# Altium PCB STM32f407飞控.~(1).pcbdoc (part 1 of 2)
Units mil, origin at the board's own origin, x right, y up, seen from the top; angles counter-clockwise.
Board outline 2007.87 x 2007.87 mil, 2 copper layers (Top Layer, Bottom Layer); 91 components, 90 nets, 406 pads, 329 vias.
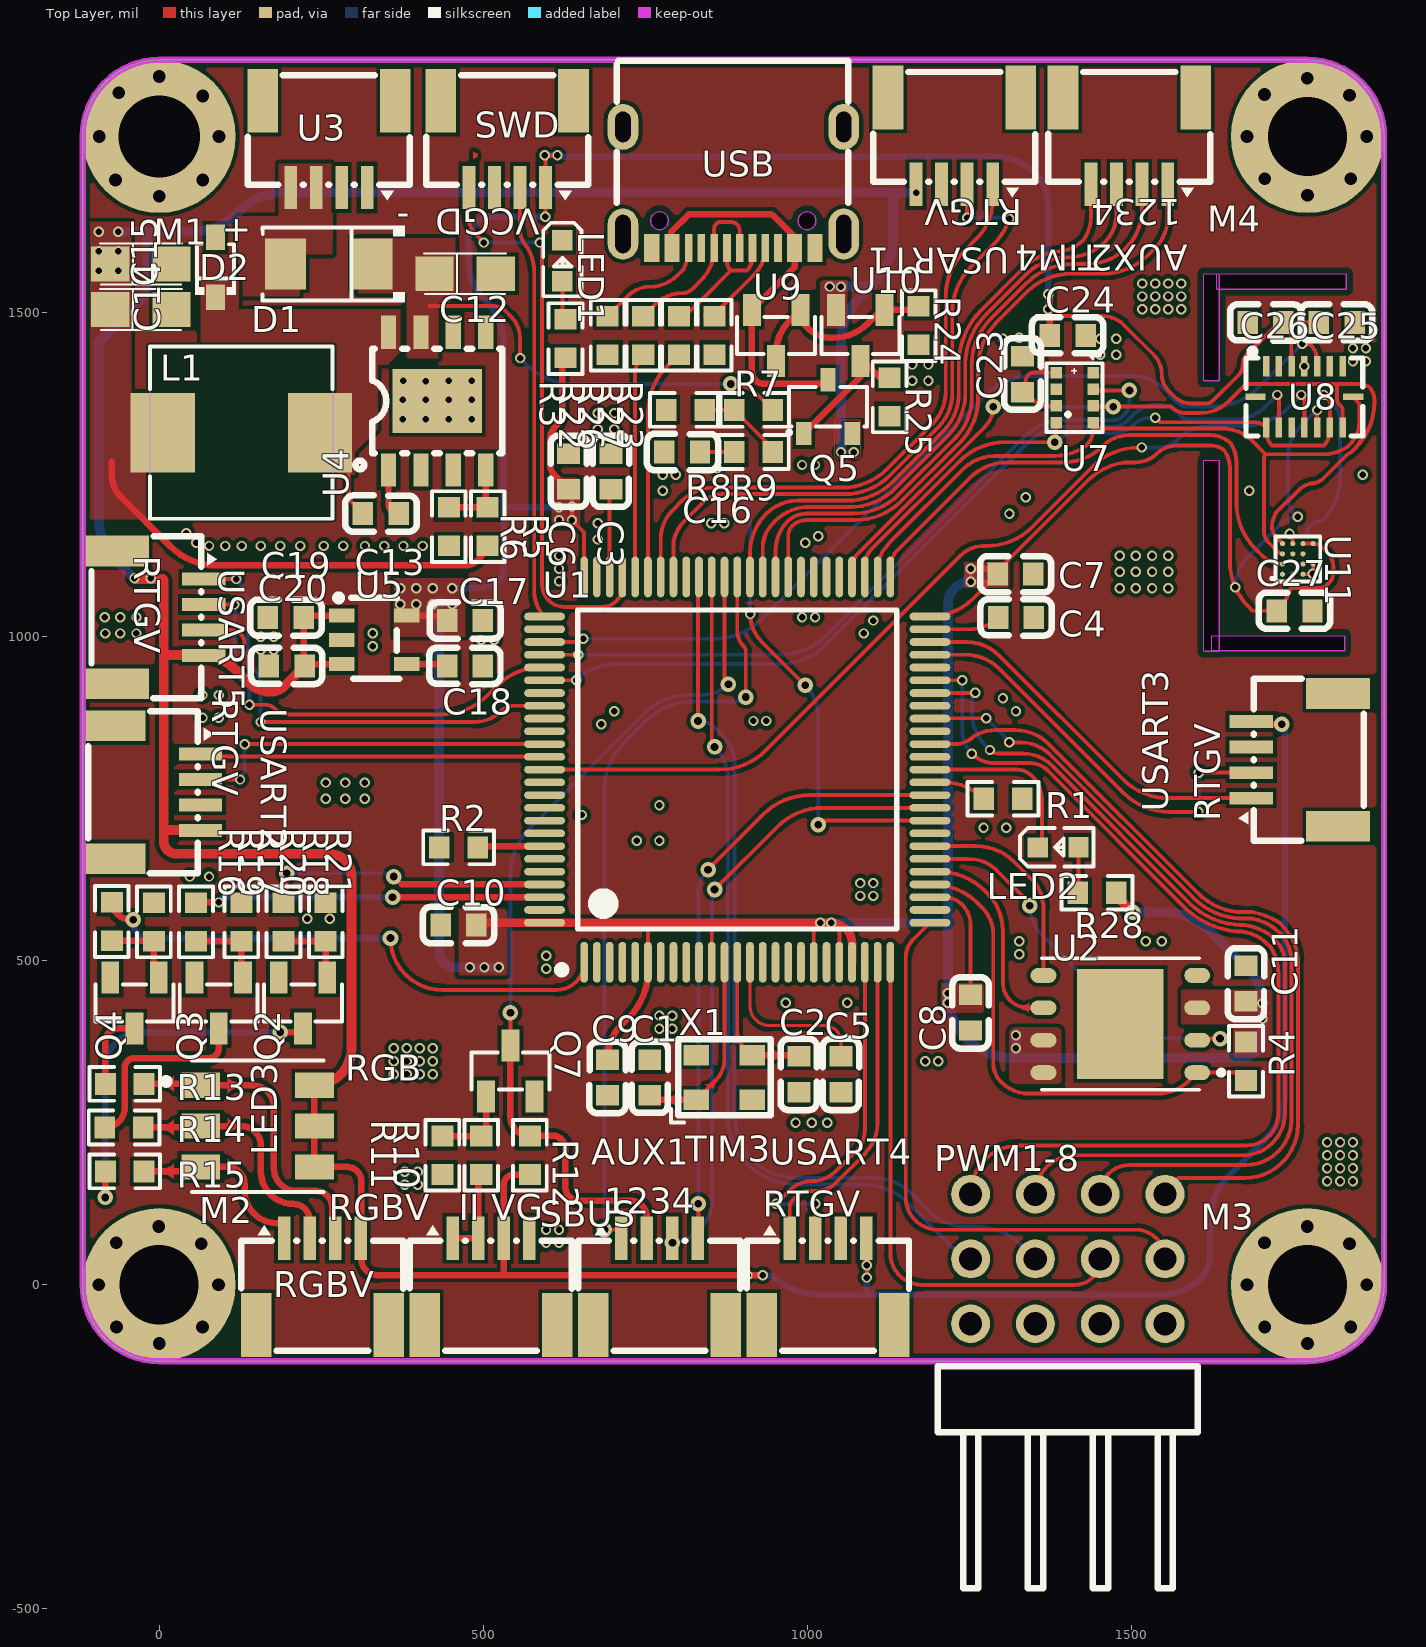
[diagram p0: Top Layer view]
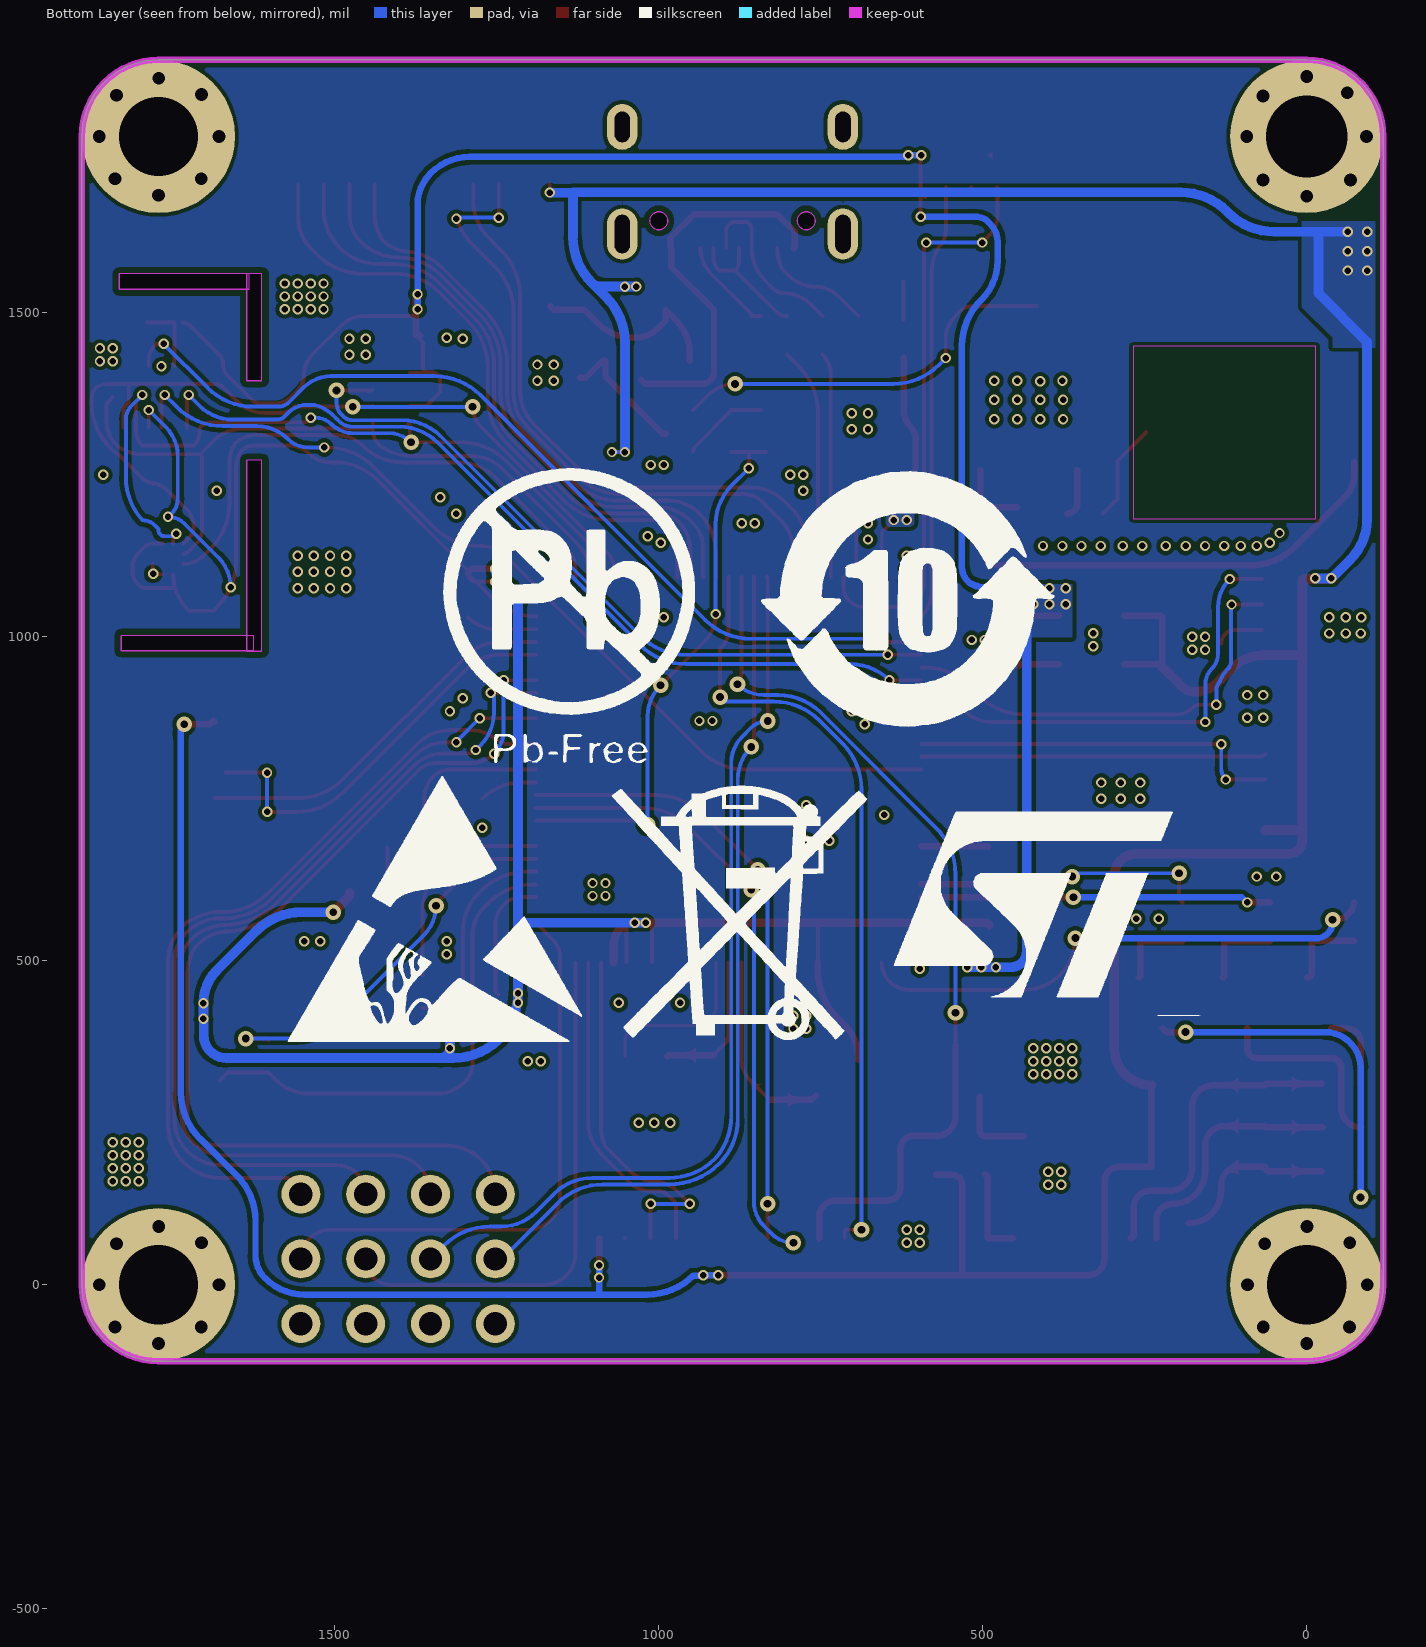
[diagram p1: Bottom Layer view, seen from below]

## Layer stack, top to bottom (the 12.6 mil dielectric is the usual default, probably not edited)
Top Solder Mask Layer: solder mask 0.4, Solder Resist, Dk 3.5
Top Layer: signal copper 1.4
Dielectric1: dielectric 12.6, FR-4, Dk 4.8
Bottom Layer: signal copper 1.4
Bottom Solder Mask Layer: solder mask 0.4, Solder Resist, Dk 3.5

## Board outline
-118.11,0 -118.11,1771.65 cw(c0,1771.65) 0,1889.76 1771.65,1889.76 cw(c1771.65,1771.65) 1889.76,1771.65 1889.76,0 cw(c1771.65,0) 1771.65,-118.11 0,-118.11 cw(c0,0)
cut-out: 1631.89,1559.76 1831.89,1559.76 1831.89,1536.14 1631.89,1536.14
cut-out: 1611.89,1559.76 1635.51,1559.76 1635.51,1394.76 1611.89,1394.76
cut-out: 1611.89,1272.26 1635.51,1272.26 1635.51,977.26 1611.89,977.26
cut-out: 1624.25,977.95 1624.25,1001.57 1829.25,1001.57 1829.25,977.95

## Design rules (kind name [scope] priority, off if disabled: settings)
BoardOutlineClearance copperThickness1oz_1 [All] p1: gap=10 ignorepadtopadclearanceinfootprint=FALSE except(0: Arc-SplitContinuation Track-SplitContinuation SMDPad-OutlineEdge SMDPad-SplitContinuation THPad-OutlineEdge THPad-SplitContinuation Via-SplitContinuation Fill-SplitContinuation Poly-SplitContinuation Region-CutoutEdge Region-SplitContinuation Text-SplitContinuation; 5: Via-OutlineEdge; 6: Track-CutoutEdge SMDPad-CutoutEdge THPad-CutoutEdge Via-CutoutEdge; 11.8: Track-OutlineEdge Fill-OutlineEdge Fill-CutoutEdge Poly-OutlineEdge Region-OutlineEdge Text-OutlineEdge)
BoardOutlineClearance copperThickness2oz_1 [All] p2: gap=10 ignorepadtopadclearanceinfootprint=FALSE except(0: Arc-SplitContinuation Track-SplitContinuation SMDPad-SplitContinuation THPad-SplitContinuation Via-SplitContinuation Fill-SplitContinuation Poly-SplitContinuation Region-SplitContinuation Text-SplitContinuation; 6: Track-CutoutEdge SMDPad-CutoutEdge THPad-CutoutEdge Via-CutoutEdge Region-CutoutEdge; 11.8: Track-OutlineEdge SMDPad-OutlineEdge THPad-OutlineEdge Via-OutlineEdge Fill-OutlineEdge Fill-CutoutEdge Poly-OutlineEdge Region-OutlineEdge Text-OutlineEdge)
Clearance copperThickness1oz [(InNet('$1N2322') OR InNet('GND') OR InNet('$1N2327') OR InNet('$1N2549') OR InNet('$1N2655') OR InNet('NRST') OR InNet('+3V3') OR InNet('VCC_IN') OR InNet('$2N671') OR InNet('$2N634') OR InNet('+5V') OR InNet('POWER_ADC') OR InNet('$2N3106') OR InNet('$2N276') OR InNet('$1N3163') OR InNet('$2N1707') OR InNet('$2N2658') OR InNet('$2N2848') OR InNet('$2N2660') OR InNet('$2N2902') OR InNet('$2N2662') OR InNet('$2N2909') OR InNet('$1N1694') OR InNet('$1N2458') OR InNet('SPI1_NSS') OR InNet('$2N953') OR InNet('$2N1448') OR InNet('SBUS_IN') OR InNet('LED_3') OR InNet('LED_2') OR InNet('LED_1') OR InNet('TIM10_CH1') OR InNet('GYR_INT') OR InNet('USART2_RX') OR InNet('USART2_TX') OR InNet('USART5_RX') OR InNet('SPI2_CS1') OR InNet('USART5_TX') OR InNet('SPI2_CS3') OR InNet('SPI2_CS2') OR InNet('SWCLK') OR InNet('SWDIO') OR InNet('DP') OR InNet('DM') OR InNet('USART1_RX') OR InNet('USART1_TX') OR InNet('TIM8_CH4') OR InNet('TIM8_CH3') OR InNet('TIM3_CH1') OR InNet('TIM4_CH4') OR InNet('TIM4_CH3') OR InNet('TIM4_CH2') OR InNet('TIM4_CH1') OR InNet('SPI2_MISO') OR InNet('SPI2_SCK') OR InNet('SPI2_NSS') OR InNet('TIM1_CH4') OR InNet('TIM1_CH3') OR InNet('TIM1_CH2') OR InNet('TIM1_CH1') OR InNet('TIM3_CH4') OR InNet('TIM3_CH3') OR InNet('SPI1_MOSI') OR InNet('SPI1_MISO') OR InNet('SPI1_SCK') OR InNet('TIM5_CH4') OR InNet('TIM5_CH3') OR InNet('USART4_RX') OR InNet('USART4_TX') OR InNet('X_IO_4') OR InNet('X_IO_1') OR InNet('X_IO_2') OR InNet('X_IO_3') OR InNet('LED_B') OR InNet('LED_G') OR InNet('LED_R') OR InNet('SPI2_MOSI') OR InNet('USART3_RX') OR InNet('USART3_TX') OR InNet('$2N11479') OR InNet('$2N11622') OR InNet('$2N24017') OR InNet('$2N24016') OR InNet('TIM3_CH2') OR InNet('VBUS') OR InNet('$2N11640') OR InNet('$2N11634') OR InNet('LED_4') OR InNet('$1N10901') OR InNet('DRDY'))] p1: gap=6 ignorepadtopadclearanceinfootprint=FALSE except(0: Region-Region; 4: Track-Track; 6.9: Track-Hole SMDPad-Hole THPad-Hole Via-Hole Fill-Hole Poly-Hole Region-Hole Text-Hole; 7: Arc-Arc Arc-Track Arc-SMDPad Arc-THPad Arc-Via Arc-Fill Arc-Poly Arc-Region Arc-Text Arc-Hole; 11.8: Track-Fill Fill-Region)
Clearance copperThickness2oz [All] p2: gap=6 ignorepadtopadclearanceinfootprint=FALSE except(6.9: Track-Hole SMDPad-Hole THPad-Hole Via-Hole Fill-Hole Poly-Hole Region-Hole Text-Hole; 7: Arc-Arc Arc-Track Arc-SMDPad Arc-THPad Arc-Via Arc-Fill Arc-Poly Arc-Region Arc-Text Arc-Hole; 8: Track-Track; 11.8: Track-Fill Fill-Region)
DiffPairsRouting differentialPair [All] p1: maxlimit=6 minlimit=6 mostfreqgap=6 toplayer_minwidth=5 toplayer_maxwidth=100 toplayer_prefwidth=10 bottomlayer_minwidth=5 bottomlayer_maxwidth=100 bottomlayer_prefwidth=10 maxuncoupledlength=10
PasteMaskExpansion pasteMaskExpansion [All] p1: expansion=0
PlaneConnect innerPlane [All] p1: planeconnectstyle=Relief reliefexpansion=20 reliefentries=4 reliefconductorwidth=10 reliefairgap=10
PolygonConnect copperRegion [All] p1: connectstyle=Direct reliefconductorwidth=10 reliefentries=4 polygonreliefangle="90 Angle" airgapwidth=10
RoutingVias viaSize [All] p1: holewidth=12 width=24 viastyle="Through Hole" minholewidth=10 minwidth=16 maxholewidth=248 maxwidth=393.7
SolderMaskExpansion solderMaskExpansion [All] p1: expansion=2 istentingtop=FALSE useseparateexpansions=TRUE expansionbottom=2 istentingbottom=FALSE
Width copperThickness1oz_2 [All] p1: maxlimit=100 minlimit=5 preferedwidth=6
Width copperThickness2oz_2 [All] p2: maxlimit=100 minlimit=8 preferedwidth=10
27 further rules are at their usual default settings.

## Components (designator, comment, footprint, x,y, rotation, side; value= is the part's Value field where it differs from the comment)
C1 "CL10C200JB8NNNC" C0603 756.89,319.76 r270 top
C2 "CL10C200JB8NNNC" C0603 986.89,324.76 r90 top
C3 "CC0603KRX7R9BB104" C0603 696.89,1254.76 r270 top
C4 "CC0603KRX7R9BB104" C0603 1321.89,1029.76 r180 top
C5 "CC0603KRX7R9BB104" C0603 1051.89,324.76 r90 top
C6 "CC0603KRX7R9BB104" C0603 631.89,1254.76 r270 top
C7 "CC0603KRX7R9BB104" C0603 1321.2,1096.34 r180 top
C8 "CC0603KRX7R9BB104" C0603 1251.89,419.76 r90 top
C9 "CC0603KRX7R9BB104" C0603 691.89,319.76 r90 top
C10 "CC0603KRX7R9BB104" C0603 461.89,554.76 r0 top
C11 "CL10A475KO8NNNC" C0603 1676.89,464.76 r90 top
C12 "TAJC107K016RNJ" CAP-SMD_L6.0-W3.2-R-RD 471.89,1559.76 r0 top
C13 "CC0603KRX7R9BB104" C0603 341.89,1189.76 r180 top
C14 "TAJA106K016RNJ" CAP-SMD_L3.2-W1.6-RD-C7171 -28.11,1504.76 r0 top
C15 "TAJA476K006RNJ" CASE-A_3216 -28.11,1574.76 r0 top
C16 "CC0603KRX7R9BB104" C0603 806.89,1284.76 r180 top
C17 "CC0603KRX7R9BB104" C0603 471.89,954.76 r0 top
C18 "CL10A106MA8NRNC" C0603 471.89,1024.76 r180 top
C19 "CC0603KRX7R9BB104" C0603 195.33,1029.23 r180 top
C20 "CL10A475KO8NNNC" C0603 196.89,954.76 r0 top
C23 "CL10A106MA8NRNC" C0603 1331.89,1404.76 r270 top
C24 "CC0603KRX7R9BB104" C0603 1401.89,1464.76 r0 top
C25 "CC0603KRX7R9BB104" C0603 1816.89,1484.76 r0 top
C26 "CC0603KRX7R9BB104" C0603 1706.89,1484.76 r180 top
C27 "CC0603KRX7R9BB104" C0603 1751.89,1039.76 r0 top
D1 "SS34_C8678" SMA_L4.3-W2.6-LS5.2-RD 261.89,1574.76 r180 top
D2 "1N4007WS" SOD-323_L1.8-W1.3-LS2.5-RD 86.89,1569.76 r90 top
L1 "SMMS0630-220M" IND-SMD_L7.3-W6.6_MHCI06030 126.89,1314.76 r0 top
LED1 "19-213/Y2C-CQ2R2L/3T(CY)" LED0603-RD-YELLOW 621.89,1579.76 r270 top
LED2 "19-213/Y2C-CQ2R2L/3T(CY)" LED0603-RD-YELLOW 1386.89,674.76 r0 top
LED3 "XL-5050RGBC-KS" LED-ARRAY-SMD_6P-L5.0-W5.0-TL-RD 151.89,244.76 r0 top
M1 "M3螺丝" m3_bd6.2#1 0,1771.65 r0 top
M2 "M3螺丝" m3_bd6.2#2 0,0 r0 top
M3 "M3螺丝" m3_bd6.2#2 1771.65,0 r0 top
M4 "M3螺丝" m3_bd6.2#2 1771.65,1771.65 r0 top
PWM1-8 "排针 2.54MM 3*4P 弯针" HDR-TH_12P-P2.54-H-M-R3-C4-S2.54-N 1401.89,39.76 r0 top
Q2 "SI2310A" SOT-23-3_L2.9-W1.3-P0.95-LS2.4-BR 221.89,434.76 r90 top
Q3 "SI2310A" SOT-23-3_L2.9-W1.3-P0.95-LS2.4-BR 91.89,434.76 r90 top
Q4 "SI2310A" SOT-23-3_L2.9-W1.3-P0.95-LS2.4-BR -38.11,434.76 r90 top
Q5 "AO3401_C727156" SOT-23-3_L2.9-W1.4-P1.90-LS2.6-BR 1031.89,1354.76 r270 top
Q7 "SS8050_C7420370" SOT-23-3_L2.9-W1.3-P1.90-LS2.4-BR 541.89,329.76 r270 top
R1 "0603WAF1002T5E" R0603 1301.89,749.76 r0 top
R2 "0603WAF1002T5E" R0603 461.89,674.76 r180 top
R3 "0603WAF1002T5E" R0603 626.89,1459.76 r270 top
R4 "0603WAF4701T5E" R0603 1676.89,344.76 r90 top
R5 "0603WAF5102T5E" R0603 506.89,1169.76 r270 top
R6 "0603WAF1502T5E" R0603 446.89,1169.76 r90 top
R7 "0603WAF1002T5E" R0603 916.89,1349.76 r0 top
R8 "0603WAF1001T5E" R0603 811.89,1349.76 r0 top
R9 "0603WAF1001T5E" R0603 916.89,1284.76 r0 top
R10 "0603WAF1001T5E" R0603 496.89,199.76 r270 top
R11 "0603WAF1002T5E" R0603 436.89,199.76 r270 top
R12 "0603WAF1002T5E" R0603 571.89,199.76 r90 top
R13 "0603WAF5100T5E" R0603 -53.11,309.76 r0 top
R14 "0603WAF5100T5E" R0603 -54.18,242.6 r0 top
R15 "0603WAF5100T5E" R0603 -53.11,174.76 r0 top
R16 "0603WAF1001T5E" R0603 -73.11,560.44 r270 top
R17 "0603WAF1001T5E" R0603 56.89,559.76 r270 top
R18 "0603WAF1001T5E" R0603 191.89,559.76 r270 top
R19 "0603WAF1002T5E" R0603 -8.11,559.76 r270 top
R20 "0603WAF1002T5E" R0603 126.89,559.76 r270 top
R21 "0603WAF1002T5E" R0603 256.89,559.76 r270 top
R22 "0603WAF5101T5E" R0603 691.89,1464.76 r270 top
R23 "0603WAF5101T5E" R0603 856.89,1464.76 r270 top
R24 "0603WAF1002T5E" R0603 1171.89,1479.76 r90 top
R25 "0603WAF1002T5E" R0603 1126.89,1369.76 r90 top
R26 "0603WAF1002T5E" R0603 746.89,1464.76 r270 top
R27 "0603WAF1002T5E" R0603 801.89,1464.76 r270 top
R28 "0603WAF1002T5E" R0603 1446.89,604.76 r0 top
RGB "ZX-SH1.0-4PWT" CONN-SMD_4P-P1.00_MEGASTAR_ZX-SH1.0-4PWT 251.89,4.76 r0 top
SBUS "ZX-SH1.0-4PWT" CONN-SMD_4P-P1.00_MEGASTAR_ZX-SH1.0-4PWT 511.89,4.76 r0 top
SWD "ZX-SH1.0-4PWT" CONN-SMD_4P-P1.00_MEGASTAR_ZX-SH1.0-4PWT 536.89,1759.76 r180 top
TIM3 "ZX-SH1.0-4PWT" CONN-SMD_4P-P1.00_MEGASTAR_ZX-SH1.0-4PWT 771.89,4.76 r0 top
TIM4 "ZX-SH1.0-4PWT" CONN-SMD_4P-P1.00_MEGASTAR_ZX-SH1.0-4PWT 1496.89,1764.76 r180 top
U1 "STM32F407VET6" LQFP-100_L14.0-W14.0-P0.50-LS16.0-BL 891.89,794.76 r0 top
U2 "W25Q32JVZPIQ" WSON-8_L6.0-W5.0-P1.27-BL-EP 1482.95,402.22 r90 top
U3 "ZX-SH1.0-4PWT" CONN-SMD_4P-P1.00_MEGASTAR_ZX-SH1.0-4PWT 261.89,1759.76 r180 top
U4 "TPS5430DDAR" ESOP-8_L4.9-W3.9-P1.27-LS6.0-TL-EP 428.82,1363.29 r90 top
U5 "MIC5219-3.3YM5-TR" SOT-23-5_L3.0-W1.7-P0.95-LS2.8-TL 331.89,994.76 r0 top
U7 "SPL06-001_C2684428" SENSOR-SMD_SPL06-001 1412.42,1368.63 r90 top
U8 "BMI088" LGA-16_L4.5-W3.0-P0.50-BL 1766.89,1369.76 r270 top
U9 "SS8550_C7420371" SOT-23-3_L2.9-W1.3-P1.90-LS2.4-BR 951.89,1464.76 r90 top
U10 "SS8550_C7420371" SOT-23-3_L2.9-W1.3-P1.90-LS2.4-BR 1081.89,1464.76 r90 top
U11 "AK09915C" BGA-14_L1.6-W1.6-BR-AK09915C 1756.89,1119.76 r270 top
USART1 "ZX-SH1.0-4PWT" CONN-SMD_4P-P1.00_MEGASTAR_ZX-SH1.0-4PWT 1226.89,1764.76 r180 top
USART2 "ZX-SH1.0-4PWT" CONN-SMD_4P-P1.00_MEGASTAR_ZX-SH1.0-4PWT -3.11,759.76 r270 top
USART3 "ZX-SH1.0-4PWT" CONN-SMD_4P-P1.00_MEGASTAR_ZX-SH1.0-4PWT 1751.89,809.76 r90 top
USART4 "ZX-SH1.0-4PWT" CONN-SMD_4P-P1.00_MEGASTAR_ZX-SH1.0-4PWT 1031.89,4.76 r0 top
USART5 "ZX-SH1.0-4PWT" CONN-SMD_4P-P1.00_MEGASTAR_ZX-SH1.0-4PWT 1.89,1029.76 r270 top
USB "TYPE-C 16PIN 2MD(073)" USB-C-SMD_TYPE-C-6PIN-2MD-073 885.83,1692.91 r180 top
X1 "X32258MOB4SI" OSC-SMD_4P-L3.2-W2.5-BL 871.89,319.76 r0 top

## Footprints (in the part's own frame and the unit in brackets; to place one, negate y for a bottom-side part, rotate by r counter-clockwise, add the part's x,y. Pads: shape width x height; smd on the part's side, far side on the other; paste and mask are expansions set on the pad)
BGA-14_L1.6-W1.6-BR-AK09915C [mm]
  round 0.2 smd: A1(0.6,-0.6) A2(0.2,-0.6) A3(-0.2,-0.6) A4(-0.6,-0.6) B1(0.6,-0.2) B3(-0.2,-0.2) B4(-0.6,-0.2) C1(0.6,0.2) C2(0.2,0.2) C3(-0.2,0.2) C4(-0.6,0.2) D1(0.6,0.6) D2(0.2,0.6) D4(-0.6,0.6)
  silkscreen extent -0.88,-1.07 0.88,0.88
C0603 [mm]
  rect 0.8x0.9 smd: 1(-0.7,0) 2(0.7,0)
  silkscreen extent -1.41,-0.71 1.39,0.72
CAP-SMD_L3.2-W1.6-RD-C7171 [mm]
  rect 1.5x1.359 smd: 1(-1.2,0) 2(1.2,0)
  silkscreen extent -1.6,-0.8 1.6,0.8
CAP-SMD_L6.0-W3.2-R-RD [mil]
  rect 59.05x53.5 smd: 1(-47.24,0) 2(47.24,0)
  silkscreen extent -63,-32 63,32
CASE-A_3216 [mil]
  rect 59.05x53.5 smd: 1(-47.24,0) 2(47.24,0)
  silkscreen extent -63,-32 63,32
CONN-SMD_4P-P1.00_MEGASTAR_ZX-SH1.0-4PWT [mm]
  rect 0.5x1.7 smd paste+0 mask+0.05: 1(-1.5,1.7) 2(-0.5,1.7) 3(0.5,1.7) 4(1.5,1.7)
  rect 1.2x2.5 smd paste+0 mask+0.05: 5(2.6,-1.7) 6(-2.6,-1.7)
  silkscreen extent -3.17,-2.7 3.18,2.21
ESOP-8_L4.9-W3.9-P1.27-LS6.0-TL-EP [mm]
  rect 1.3x0.6 smd: 1(-2.7,1.905) 2(-2.7,0.635) 3(-2.7,-0.635) 4(-2.7,-1.905) 5(2.7,-1.905) 6(2.7,-0.635) 7(2.7,0.635) 8(2.7,1.905)
  rect 2.5x3.5 smd: 9(0,0)
  silkscreen extent -2.67,-2.55 2.05,3.2
HDR-TH_12P-P2.54-H-M-R3-C4-S2.54-N [mil]
  round 60 hole 36 paste+0 mask+1.97: 1(-150,100) 2(-50,100) 3(50,100) 4(150,100) 5(150,0) 6(50,0) 7(-50,0) 8(-150,0) 9(-150,-100) 10(-50,-100) 11(50,-100) 12(150,-100)
  silkscreen extent -201,-508 201,-165
IND-SMD_L7.3-W6.6_MHCI06030 [mm]
  rect 2.524x3.12 smd: 1(-3.078,0) 2(3.078,0)
  silkscreen extent -3.58,-3.38 3.58,3.38
LED0603-RD-YELLOW [mm]
  rect 0.8x0.8 smd: 1(-0.799,-0.003) 2(0.799,0.003)
  silkscreen extent -1.49,-0.75 1.39,0.76
LED-ARRAY-SMD_6P-L5.0-W5.0-TL-RD [mil]
  rect 60x38.58 smd: 1(-87.7,62.99) 2(-87.7,0) 3(-87.7,-62.99) 4(87.7,-62.99) 5(87.7,0) 6(87.7,62.99)
  silkscreen extent -146,-101 101,101
LGA-16_L4.5-W3.0-P0.50-BL [mm]
  rect 0.8x0.25 smd: 1(-1.2,-1.498) 2(-1.2,-0.998) 3(-1.2,-0.498) 4(-1.2,0.002) 5(-1.2,0.502) 6(-1.2,1.002) 7(-1.2,1.502) 9(1.2,1.502) 10(1.2,1.002) 11(1.2,0.502) 12(1.2,0.002) 13(1.2,-0.498) 14(1.2,-0.998) 15(1.2,-1.498)
  rect 0.25x0.8 smd: 8(0,1.915) 16(0,-1.915)
  silkscreen extent -1.89,-2.29 1.52,2.29
LQFP-100_L14.0-W14.0-P0.50-LS16.0-BL [mm]
  oval 0.3x1.6 smd paste-100 mask+0.051: 1(-6,-7.55) 2(-5.5,-7.55) 3(-5,-7.55) 4(-4.5,-7.55) 5(-4,-7.55) 6(-3.5,-7.55) 7(-3,-7.55) 8(-2.5,-7.55) 9(-2,-7.55) 10(-1.5,-7.55) 11(-1,-7.55) 12(-0.5,-7.55) 13(0,-7.55) 14(0.5,-7.55) 15(1,-7.55) 16(1.5,-7.55) 17(2,-7.55) 18(2.5,-7.55) 19(3,-7.55) 20(3.5,-7.55) 21(4,-7.55) 22(4.5,-7.55) 23(5,-7.55) 24(5.5,-7.55) 25(6,-7.55) 51(6,7.55) 52(5.5,7.55) 53(5,7.55) 54(4.5,7.55) 55(4,7.55) 56(3.5,7.55) 57(3,7.55) 58(2.5,7.55) 59(2,7.55) 60(1.5,7.55) 61(1,7.55) 62(0.5,7.55) 63(0,7.55) 64(-0.5,7.55) 65(-1,7.55) 66(-1.5,7.55) 67(-2,7.55) 68(-2.5,7.55) 69(-3,7.55) 70(-3.5,7.55) 71(-4,7.55) 72(-4.5,7.55) 73(-5,7.55) 74(-5.5,7.55) 75(-6,7.55)
  oval 1.6x0.3 smd paste-100 mask+0.051: 26(7.55,-6) 27(7.55,-5.5) 28(7.55,-5) 29(7.55,-4.5) 30(7.55,-4) 31(7.55,-3.5) 32(7.55,-3) 33(7.55,-2.5) 34(7.55,-2) 35(7.55,-1.5) 36(7.55,-1) 37(7.55,-0.5) 38(7.55,0) 39(7.55,0.5) 40(7.55,1) 41(7.55,1.5) 42(7.55,2) 43(7.55,2.5) 44(7.55,3) 45(7.55,3.5) 46(7.55,4) 47(7.55,4.5) 48(7.55,5) 49(7.55,5.5) 50(7.55,6) 76(-7.55,6) 77(-7.55,5.5) 78(-7.55,5) 79(-7.55,4.5) 80(-7.55,4) 81(-7.55,3.5) 82(-7.55,3) 83(-7.55,2.5) 84(-7.55,2) 85(-7.55,1.5) 86(-7.55,1) 87(-7.55,0.5) 88(-7.55,0) 89(-7.55,-0.5) 90(-7.55,-1) 91(-7.55,-1.5) 92(-7.55,-2) 93(-7.55,-2.5) 94(-7.55,-3) 95(-7.55,-3.5) 96(-7.55,-4) 97(-7.55,-4.5) 98(-7.55,-5) 99(-7.55,-5.5) 100(-7.55,-6)
  silkscreen extent -7.03,-8 6.25,6.25
m3_bd6.2#1 [mm]
  round 6 hole 3.2: 1(0,0)
m3_bd6.2#2 [mm]
  round 6 hole 3.1: 1(0,0)
OSC-SMD_4P-L3.2-W2.5-BL [mm]
  rect 1x0.8 smd: 1(-1.1,-0.875) 2(1.1,-0.875) 3(1.1,0.875) 4(-1.1,0.875)
  silkscreen extent -2.08,-1.77 1.83,1.5
R0603 [mil]
  rect 31.75x34.02 smd paste-3937.01 mask+2: 1(-29.66,0) 2(29.66,0)
  silkscreen extent -55,-26 55,26
SENSOR-SMD_SPL06-001 [mm]
  rect 0.45x0.45 smd: 1(0.975,-0.725) 2(0.325,-0.725) 3(-0.325,-0.725) 4(-0.975,-0.725) 5(-0.975,0.725) 6(-0.325,0.725) 7(0.325,0.725) 8(0.975,0.725)
  silkscreen extent -1.35,-1.1 1.64,1.1
SMA_L4.3-W2.6-LS5.2-RD [mm]
  rect 1.6x2 smd: 1(-1.7,-0.008) 2(1.7,-0.009)
  silkscreen extent -2.98,-1.5 2.6,1.5
SOD-323_L1.8-W1.3-LS2.5-RD [mm]
  rect 1x0.75 smd: 1(-1.173,0) 2(1.173,0)
  silkscreen extent -1.08,-0.8 0.9,0.8
SOT-23-3_L2.9-W1.3-P0.95-LS2.4-BR [mm]
  rect 1.25x0.7 smd: 1(1,-0.95) 2(1,0.95) 3(-1,0)
  silkscreen extent -0.73,-1.53 0.73,1.53
SOT-23-3_L2.9-W1.3-P1.90-LS2.4-BR [mm]
  rect 1.25x0.7 smd: 1(1,-0.95) 2(1,0.95) 3(-1,0)
  silkscreen extent -0.73,-1.53 0.73,1.53
SOT-23-3_L2.9-W1.4-P1.90-LS2.6-BR [mm]
  rect 0.91x0.6 smd: 1(1.055,-0.955) 2(1.055,0.955) 3(-1.055,0)
  silkscreen extent -0.78,-1.6 1.09,1.53
SOT-23-5_L3.0-W1.7-P0.95-LS2.8-TL [mm]
  rect 1x0.55 smd: 1(-1.271,0.95) 2(-1.271,0) 3(-1.271,-0.95) 4(1.271,-0.95) 5(1.271,0.95)
  silkscreen extent -1.52,-1.52 0.97,1.78
USB-C-SMD_TYPE-C-6PIN-2MD-073 [mm]
  rect 0.6x1.1 smd paste-100 mask+0.05: 1(-3.2,2.375) 2(-2.4,2.375) 11(2.4,2.375) 12(3.2,2.375)
  rect 0.3x1.1 smd paste-100 mask+0.05: 3(-1.75,2.375) 4(-1.25,2.375) 5(-0.75,2.375) 6(-0.25,2.375) 7(0.25,2.375) 8(0.75,2.375) 9(1.25,2.375) 10(1.75,2.375)
  oval 1.2x1.8 hole 0.6 slot 1.2 at 90 deg paste+0 mask+0.05: 13(-4.325,-2.375) 14(4.325,-2.375)
  oval 1.2x2 hole 0.6 slot 1.5 at 90 deg paste+0 mask+0.05: 13(-4.325,1.825) 13(4.325,1.825)
  Board Outline Layer board cut-out: -3.24,1.305 -3.24,1.375 -3.187,1.503 -3.088,1.602 -2.96,1.655 -2.82,1.655 -2.692,1.602 -2.593,1.503 -2.54,1.375 -2.54,1.305 -2.54,1.235 -2.593,1.107 -2.692,1.008 -2.82,0.955 -2.96,0.955 -3.088,1.008 -3.187,1.107 -3.24,1.235 -3.24,1.305
  Board Outline Layer board cut-out: 2.54,1.305 2.54,1.375 2.593,1.503 2.692,1.602 2.821,1.655 2.96,1.655 3.088,1.602 3.187,1.503 3.24,1.375 3.24,1.305 3.24,1.235 3.187,1.107 3.088,1.008 2.96,0.955 2.821,0.955 2.692,1.008 2.593,1.107 2.54,1.235 2.54,1.305
  Board Outline Layer circle w0.025: c-2.89,1.305 r0.35
  Board Outline Layer circle w0.025: c2.89,1.305 r0.35
  Board Outline Layer region: -3.24,1.305 -3.24,1.375 -3.187,1.503 -3.088,1.602 -2.96,1.655 -2.82,1.655 -2.692,1.602 -2.593,1.503 -2.54,1.375 -2.54,1.305 -2.54,1.235 -2.593,1.107 -2.692,1.008 -2.82,0.955 -2.96,0.955 -3.088,1.008 -3.187,1.107 -3.24,1.235 -3.24,1.305
  Board Outline Layer region: 2.54,1.305 2.54,1.375 2.593,1.503 2.692,1.602 2.821,1.655 2.96,1.655 3.088,1.602 3.187,1.503 3.24,1.375 3.24,1.305 3.24,1.235 3.187,1.107 3.088,1.008 2.96,0.955 2.821,0.955 2.692,1.008 2.593,1.107 2.54,1.235 2.54,1.305
  silkscreen extent -4.5,-4.97 4.57,0.6
WSON-8_L6.0-W5.0-P1.27-BL-EP [mil]
  oval 22.87x40 smd: 1(-75,-118.61) 2(-25,-118.61) 3(25,-118.61) 4(75,-118.61) 5(75,118.61) 6(25,118.61) 7(-25,118.61) 8(-75,118.61)
  rect 169.29x133.86 smd: 9(0,0)
  silkscreen extent -101,-159 101,121

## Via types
v1: diameter 16, hole 10, Top Layer to Bottom Layer, 269 vias
v2: diameter 31.5, hole 19.69, Top Layer to Bottom Layer, 32 vias
v3: diameter 24, hole 12, Top Layer to Bottom Layer, 23 vias
v4: diameter 24.02, hole 12.01, Top Layer to Bottom Layer, 5 vias

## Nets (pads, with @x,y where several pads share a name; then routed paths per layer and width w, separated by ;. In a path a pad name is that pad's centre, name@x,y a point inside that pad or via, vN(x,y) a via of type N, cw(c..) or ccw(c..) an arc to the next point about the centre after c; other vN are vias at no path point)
$1N1694: R1.1 U1.37 | length 89.9
  Top Layer w6: U1.37@1189.13,775.08 1211.1,775.08 cw(c1211.1,688.64) 1218.53,774.76 cw(c1211.1,688.64) R1.1@1272.23,749.76
$1N2322: C1.2 U1.12 X1.1 | length 302.9
  Top Layer w6: X1.1@828.58,285.31 859.09,315.83 ccw(c828.19,346.72) 871.89,346.72 871.89,382.87 cw(c872.98,382.87) 872.21,383.64 U1.12@872.21,497.52
  Top Layer w10: C1.2@756.89,292.2 763.78,285.31 X1.1@828.58,285.31
$1N2327: C2.2 U1.13 X1.3 | length 225.4
  Top Layer w6: U1.13@891.89,497.52 891.89,377.52 X1.3@915.2,354.21
  Top Layer w10: X1.3@915.2,354.21 985,354.21 C2.2@986.89,352.32
$1N2458: R2.1 U1.94 | length 104.2
  Top Layer w10: R2.1@491.55,674.76 cw(c493.44,674.76) 493.44,676.65 U1.94@594.65,676.65
$1N2549: C3.2 U1.73 | length 136
  Top Layer w6: U1.73@695.04,1092 695.04,1225.35 C3.2@696.89,1227.2
$1N2655: C4.2 U1.49 | length 110.1
  Top Layer w6: U1.49@1189.13,1011.3 1249.76,1011.3 ccw(c1249.76,1074.33) 1277.11,1017.55 ccw(c1249.76,1074.33) C4.2@1294.33,1029.76
$1N3163: LED1.2 R3.1 | length 58.9
  Top Layer w6: R3.1@621.89,1489.42 622.02,1489.56 LED1.2@622.02,1548.29
$1N10901: LED2.2 R28.1 | length 70.4
  Top Layer w6: R28.1@1417.23,604.76 ccw(c1414.49,607.5) R28.1@1418.36,607.5 ; R28.1@1418.36,607.5 LED2.2@1418.36,674.9
$2N276: D1.2 U3.3 U3.4
$2N634: C13.1 U4.1 | length 76.2
  Top Layer w10: U4.1@353.82,1257 353.82,1205.39 ccw(c369.45,1205.39) C13.1@369.45,1189.76
$2N671: C13.2 D2.1 L1.2 U4.8 | length 152.4
  Top Layer w6: L1.2@248.07,1314.76 291.89,1270.94 291.89,1212.2 C13.2@314.33,1189.76
$2N953: R5.1 R6.2 U4.4 | length 113.7
  Top Layer w10: R6.2@446.89,1199.42 501.89,1199.42 ccw(c501.89,1201.35) 503.82,1201.35 U4.4@503.82,1257
$2N1448: R7.1 R8.2 R9.2 | length 134.7
  Top Layer w6: R8.2@841.55,1349.76 R7.1@887.23,1349.76 942.53,1294.46 cw(c932.84,1284.76) R9.2@946.55,1284.76
$2N1707: Q7.1 R10.1 R11.1 | length 125.3
  Top Layer w10: R11.1@436.89,229.42 R10.1@496.89,229.42 ccw(c496.89,237.02) 504.49,237.02 Q7.1@504.49,290.39
$2N2658: Q2.1 R18.2 R21.2 | length 122.3
  Top Layer w10: R18.2@191.89,530.1 R21.2@256.89,530.1 256.89,476.53 ccw(c259.29,476.53) Q2.1@259.29,474.13
$2N2660: Q3.1 R17.2 R20.2 | length 127.3
  Top Layer w10: R17.2@56.89,530.1 R20.2@126.89,530.1 126.89,476.53 ccw(c129.29,476.53) Q3.1@129.29,474.13
$2N2662: Q4.1 R16.2 R19.2 | length 125.6
  Top Layer w10: R16.2@-73.11,530.78 -8.79,530.78 cw(c-8.79,530.1) R19.2@-8.11,530.1 -8.11,481.53 ccw(c-0.71,481.53) Q4.1@-0.71,474.13
$2N2848: Q2.3 R15.1 | length 579
  Top Layer w10: v4(-83.11,134.76) -83.11,174.42 R15.1@-82.77,174.76 ; v4(186.89,389.76) 216.26,389.76 221.26,394.76 ccw(c221.26,395.39) Q2.3@221.89,395.39
  Bottom Layer w10: v4(-83.11,134.76) -83.11,334.76 cw(c-28.11,334.76) -28.11,389.76 v4(186.89,389.76)
$2N2902: Q3.3 R14.1 | length 302.5
  Top Layer w10: R14.1@-83.84,242.6 ccw(c-83.84,273.33) -53.11,273.33 -53.11,334.76 cw(c-38.11,334.76) -38.11,349.76 76.89,349.76 ccw(c76.89,364.76) 91.89,364.76 Q3.3@91.89,395.39
$2N2909: Q4.3 R13.1 | length 122
  Top Layer w10: R13.1@-82.77,309.76 cw(c-82.77,310.1) -83.11,310.1 -83.11,374.76 cw(c-62.48,374.76) -62.48,395.39 Q4.3@-38.11,395.39
$2N3106: C17.1 U5.4 | length 63.9
  Top Layer w10: U5.4@381.94,957.36 441.73,957.36 cw(c441.73,954.76) C17.1@444.33,954.76
$2N11479: R22.1 USB.10 | length 176.4
  Top Layer w6: R22.1@691.89,1494.42 723.33,1525.86 cw(c756.89,1492.3) 756.89,1539.76 ccw(c756.89,1600.89) 800.11,1557.67 808.84,1566.4 ccw(c745.43,1599.41) USB.10@816.92,1599.41
$2N11622: R23.1 USB.4 | length 146.4
  Top Layer w6: R23.1@841.89,1494.42 R23.1@853.67,1494.42 ; R23.1@856.89,1494.42 cw(c864.67,1494.42) 859.17,1499.93 918.33,1559.09 ccw(c878.01,1599.41) 919.83,1560.64 ccw(c878.01,1599.41) 927.74,1571.52 ccw(c921.26,1577.75) 930.14,1576.3 ccw(c878.01,1599.41) USB.4@935.03,1599.41
$2N11634: R26.1 USB.6 USB.8 | length 273.2
  Top Layer w6: R26.1@746.89,1494.42 764.79,1512.33 cw(c806.89,1470.23) 806.89,1529.76 ccw(c806.89,1552.32) 822.84,1536.37 835.39,1548.92 ccw(c784.9,1599.41) USB.8@856.3,1599.41 856.3,1629.18 cw(c866.89,1629.18) 866.89,1639.76 881.89,1639.76 cw(c881.89,1625.98) 895.67,1625.98 USB.6@895.67,1599.41
$2N11640: R27.1 USB.5 USB.7 | length 206.3
  Top Layer w6: R27.1@801.89,1494.42 ccw(c801.89,1517.75) 818.38,1501.25 832.35,1515.22 cw(c839.88,1510.3) 834.96,1517.83 881.89,1564.76 ; USB.7@875.98,1599.41 875.98,1579.03 ccw(c896.15,1579.03) 881.89,1564.76 ; USB.5@915.35,1599.41 915.35,1585.19 cw(c886.46,1585.19) 906.89,1564.76 881.89,1564.76
$2N24016: R24.2 U9.1 U9.3 U10.1 | length 311.2
  Top Layer w10: U9.3@951.89,1425.39 951.89,1437.06 cw(c1023.52,1437.06) 972.87,1487.72 U9.1@989.29,1504.13 989.29,1487.36 1001.62,1475.03 ccw(c1035.5,1508.91) 1035.5,1461 1039.62,1461 ccw(c1039.62,1537.13) 1093.45,1483.3 1114.29,1504.13 1161.6,1504.13 R24.2@1166.89,1509.42
$2N24017: Q5.1 R25.2 U10.3 | length 204.2
  Top Layer w10: Q5.1@989.29,1313.22 Q5.1@994.29,1313.22 1081.89,1400.82 U10.3@1081.89,1425.39 1086.26,1425.39 1112.23,1399.42 R25.2@1121.89,1399.42
+3V3: C6.2 C7.2 C8.2 C9.2 C10.2 C11.1 C18.2 C23.2 C24.1 C25.1 C26.1 C27.1 R3.2 R4.2 R28.2 SWD.1 U1.6 U1.11 U1.19 U1.21 U1.22 U1.28 U1.50 U1.75 U1.100 U2.3 U2.7 U2.8 U5.5 U7.6 U7.8 U8.3 U8.11 U11.B1 U11.C4 U11.D4 | length 8543.3
  Top Layer w6: SWD.1@588.65,1678.22 SWD.1@590.76,1680.32 ; v1(595.56,1647.98) ccw(c594.64,1648.9) 595.94,1648.9 SWD.1@595.94,1692.83 595.94,1739.2 ccw(c591.39,1739.2) v1(594.61,1742.42) v1(614.54,1742.42) ; C6.2@636.89,1222.2 v1(636.89,1179.76) 655.67,1160.98 U1.75@655.67,1092 ; 753.33,558.54 cw(c753.33,557.79) 754.09,557.79 U1.6@754.09,497.52 ; 851.28,558.54 cw(c851.28,557.3) 852.52,557.3 U1.11@852.52,497.52 ; 1008.69,558.54 cw(c1008.69,557.23) 1010,557.23 U1.19@1010,497.52 ; 1048.46,556.33 cw(c1048.46,555.43) 1049.09,556.08 cw(c1048.46,555.43) 1049.37,555.43 U1.21@1049.37,497.52 ; U1.28@1189.13,597.91 1211.45,597.91 cw(c1211.45,559.27) 1238.78,586.59 cw(c1207.11,554.93) 1251.89,554.93 1251.89,452.32 C8.2@1246.89,447.32 ; U1.50@1189.13,1030.98 ccw(c1189.13,1125.5) 1255.96,1058.67 C7.2@1282.06,1084.76 ; v1(1251.89,1104.76) v1(1251.89,1084.76) C7.2@1282.06,1084.76 ; v1(1371.89,1504.76) v1@1374.33,1502.32 ; C24.1@1374.33,1473.25 1365.84,1464.76 C24.1@1374.33,1464.76 1362.3,1452.74 cw(c1354.61,1448.07) 1363.61,1448.07 1363.61,1416.58 cw(c1354.61,1416.58) 1357.47,1408.04 cw(c1354.61,1416.58) 1354.61,1407.58 ; 1374.33,1494.76 1455.05,1494.76 cw(c1455.05,1447.8) 1488.24,1481.03 ; U7.6@1383.88,1355.84 1358.26,1355.84 1336.89,1377.2 1336.89,1393.47 cw(c1351.47,1393.47) 1347.81,1407.58 1354.61,1407.58 ; U7.8@1383.88,1407.02 1355.95,1407.02 cw(c1355.95,1408.92) 1354.61,1407.58 ; 1488.26,1481.01 1534.43,1434.84 cw(c1504.36,1404.76) 1546.89,1404.76 ccw(c1583.1,1404.76) 1557.5,1379.16 1566.89,1369.76 ccw(c1591.03,1393.91) 1591.03,1359.76 1614.82,1359.76 ccw(c1614.82,1376.83) 1626.89,1364.76 1664.82,1402.69 ccw(c1647.75,1419.76) 1671.89,1419.76 cw(c1693.62,1419.76) 1676.12,1432.64 cw(c1693.62,1419.76) 1678.25,1435.13 1723.25,1480.13 cw(c1734.45,1468.93) C26.1@1734.45,1484.76 ; U8.3@1747.29,1417 1747.29,1434.36 1746.65,1435 1746.65,1484.76 C25.1@1789.33,1484.76 ; U11.B1@1749.02,1096.14 cw(c1672.51,1096.14) 1746.02,1074.93 ; U11.C4@1764.76,1143.38 U11.D4@1780.51,1143.38 cw(c1780.51,1124.65) 1793.76,1137.9 1801.89,1129.76 cw(c1777.75,1105.62) 1811.89,1105.62 1811.89,1099.76 cw(c1787.75,1099.76) 1804.82,1082.69 1801.89,1079.76 cw(c1789.82,1091.83) 1789.82,1074.76 1746.42,1074.76 cw(c1746.42,1075.33) 1746.02,1074.93 ; U8.11@1786.66,1322.52 v1(1786.66,1349.49) ; C7.2@1282.06,1084.76 ccw(c1282.06,1096.34) C7.2@1293.64,1096.34 ; C7.2@1282.06,1084.76 C7.2@1293.64,1096.34 ; C7.2@1293.64,1096.34 1293.64,1101.51 1432.66,1240.53 cw(c1503.37,1169.82) 1489.05,1268.79 1506.62,1268.79 ccw(c1506.62,1315.39) 1516.36,1269.82 ccw(c1506.62,1315.39) 1539.57,1282.44 cw(c1569.32,1252.69) 1569.32,1294.76 1623.2,1294.76 cw(c1623.2,1265.31) 1644.02,1286.14 cw(c1605.51,1260.29) 1651.89,1260.29 1651.89,1116.19 ccw(c1751.89,1116.19) v1(1660.27,1076.12) ccw(c1751.89,1116.19) 1681.18,1045.47 1686.89,1039.76 C27.1@1724.33,1039.76 1726.61,1042.05 ccw(c1672.51,1096.14) 1746.02,1074.93
  Top Layer w10: U5.5@381.94,1032.17 436.92,1032.17 cw(c436.92,1024.76) C18.2@444.33,1024.76 ; R3.2@621.89,1430.1 621.89,1349.84 cw(c585.49,1349.84) 611.23,1324.1 ccw(c630.68,1304.66) 603.17,1304.66 603.17,1264.75 ccw(c624.48,1264.75) 609.41,1249.68 C6.2@631.89,1227.2 ; C9.2@691.89,347.32 691.89,350.56 cw(c762.39,350.56) 712.54,400.41 724.8,412.67 ccw(c654.09,483.39) 754.09,483.39 U1.6@754.09,497.52 ; v1(1251.89,1104.76) 1285.21,1104.76 cw(c1285.21,1096.34) C7.2@1293.64,1096.34 ; v1(1371.86,1528.35) 1374.33,1525.87 1374.33,1502.32 1374.33,1494.76 1374.33,1473.25 C24.1@1374.33,1464.76
  Top Layer w13: C10.2@489.45,554.76 493.23,558.54 U1.100@594.65,558.54 753.33,558.54 851.28,558.54 1008.69,558.54 v1(1019.79,558.54) v1(1036.71,558.54) cw(c1036.71,526.19) 1048.46,556.33 cw(c1036.71,526.2) 1049.09,556.08 cw(c1036.71,526.19) 1069.06,526.19 U1.22@1069.06,497.52
  Top Layer w15: R28.2@1476.55,604.76 ccw(c1487.8,604.76) 1479.84,596.81 v3(1501.89,574.76)
  Bottom Layer w6: v1(1660.27,1076.12) cw(c1725.5,1076.12) 1679.37,1122.25 1731.28,1174.16 cw(c1756.89,1148.55) v1(1756.89,1184.76) cw(c1776.06,1213.05) 1741.89,1213.05 1741.89,1278.69 cw(c1804.73,1278.69) 1760.29,1323.13 v1(1786.66,1349.49)
  Bottom Layer w10: v1(451.89,1074.76) 486.89,1074.76 ccw(c486.89,1144.76) 501.1,1076.22 ; v1(594.61,1742.42) v1(614.54,1742.42) 616.98,1739.99 1291.26,1739.99 cw(c1291.26,1654.51) 1351.7,1714.95 cw(c1302.97,1666.21) 1371.89,1666.21 v1(1371.86,1528.35) v1(1371.89,1504.76) ; v1(595.56,1647.98) 514.02,1647.98 ccw(c514.02,1606.63) 495.02,1643.36 488.68,1637.01 ccw(c517.14,1608.55) 476.89,1608.55 476.89,1580.12 ccw(c562.25,1580.12) 501.89,1519.76 502.6,1519.05 cw(c431.89,1448.34) 531.89,1448.34 531.89,1199.57 ; v1(616.89,1199.76) 532.08,1199.76 ccw(c532.08,1199.57) 531.89,1199.57 ; 501.1,1076.22 ccw(c501.1,1107.01) 521.4,1083.86 ; 501.1,1076.22 ccw(c486.89,1144.76) 521.4,1083.86 ; 521.4,1083.86 ccw(c501.1,1107.01) 531.89,1107.01 531.89,1199.57
  Bottom Layer w15: 431.89,1054.76 431.89,514.76 ccw(c456.89,514.76) 456.89,489.76 v1(479.46,489.76) v1(501.89,489.76) v1(523.95,489.76) ; v1(1019.79,558.54) v1(1036.71,558.54) 1216.89,558.58 ; v1(1251.89,1084.76) ccw(c1251.89,1049.76) 1243.23,1083.67 ; v1(1251.89,1104.76) cw(c1221.89,1104.76) 1246.85,1088.12 cw(c1221.89,1104.76) 1243.23,1083.67 ; v1(1321.89,364.76) ccw(c1336.89,364.76) 1336.89,349.76 ; v3(1501.89,574.76) 1550.47,574.76 cw(c1550.47,474.76) 1621.18,545.47 1681.89,484.76 cw(c1632.87,435.74) 1702.2,435.74 v1(1702.2,434.17) v1(1702.2,410.07) ccw(c1702.2,409.76) 1701.89,409.76 1701.89,384.76 cw(c1666.89,384.76) 1666.89,349.76 1336.89,349.76 ; 1216.89,558.58 1216.89,1049.76 cw(c1251.89,1049.76) 1228.07,1075.41 cw(c1251.89,1049.76) 1243.23,1083.67 ; 1216.89,558.58 v1(1216.89,449.76) ccw(c1316.89,449.76) 1218,434.93 ccw(c1316.89,449.76) 1316.89,349.76 1336.89,349.76
  Bottom Layer w16: v1(1321.89,364.76) v1(1321.89,384.76)
  other v1: 1216.89,434.76 371.89,1049.76 396.89,1049.76 421.89,1049.76 451.89,1049.76 371.89,1074.76 396.89,1074.76 421.89,1074.76 616.89,1179.76 637,1200.64
+5V: C14.1 C15.1 C19.1 C20.2 L1.1 LED3.4 LED3.5 LED3.6 Q5.2 R5.2 R12.1 RGB.4 SBUS.3 U5.1 U5.3 U10.2 USART1.4 USART2.4 USART3.4 USART4.4 USART5.4 | length 7614.6
  Top Layer w6: v1(1091.89,11.04) v1(1091.89,29.76) ; v1(1167.83,1685.06) USART1.4@1167.83,1697.83
  Top Layer w10: -73.11,1269.76 -73.11,1248.11 ccw(c-28.83,1248.11) -60.14,1216.79 17.6,1139.05 ccw(c88.31,1209.76) 88.31,1109.76 471.55,1109.76 ccw(c471.55,1140.1) R5.2@501.89,1140.1 ; LED3.6@239.59,307.75 LED3.5@239.59,244.76 LED3.4@239.59,181.77 289.88,181.77 cw(c289.88,159.76) 311.89,159.76 RGB.4@311.89,72.63 ; U5.3@281.83,957.36 227.04,957.36 ccw(c227.04,954.76) C20.2@224.45,954.76 cw(c224.45,956.32) 222.89,956.32 C19.1@222.89,1029.23 cw(c225.84,1029.23) 225.84,1032.17 U5.1@281.83,1032.17 ; RGB.4@310.95,71.69 ccw(c310.95,72.63) RGB.4@311.89,72.63 ; R12.1@571.89,170.1 cw(c571.55,170.1) 571.55,169.76 546.89,169.76 ccw(c546.89,154.45) 531.58,154.45 SBUS.3@531.58,71.69 cw(c531.58,71.5) 531.77,71.5 531.77,14.76 ; v1(930.96,14.76) v1(907.76,14.76) 531.77,14.76 ; USART4.4@1090.95,71.69 cw(c1088.68,69.42) 1091.89,69.42 v1(1091.89,29.76) ; USART3.4@1684.96,868.82 cw(c1687.23,866.55) 1687.23,869.76 1692.23,864.76 v3(1731.89,864.76) ; RGB.4@311.89,72.63 311.89,39.76 ccw(c336.89,39.76) 336.89,14.76 531.77,14.76
  Top Layer w15: v1(-38.11,1089.76) ccw(c-35.82,1092.06) -35.82,1088.81 5.85,1088.81 6.89,1087.78 6.89,971.51 ; USART2.4@63.82,700.7 ccw(c61.34,698.22) 61.34,701.73 6.89,701.73 ; USART5.4@68.82,970.7 ccw(c66.87,968.75) USART5.4@67.46,971.45 ; C20.2@224.45,954.76 193.33,923.65 cw(c171.89,945.09) 171.89,914.76 cw(c171.89,963.05) 137.75,928.91 116.89,949.76 ccw(c64.38,897.26) USART5.4@67.46,971.45 ; LED3.6@239.59,307.75 ccw(c239.59,365.05) 296.89,365.05 296.89,630.75 ccw(c262.88,630.75) 262.88,664.76 26.89,664.76 cw(c26.89,684.76) 6.89,684.76 6.89,701.73 ; 6.89,701.73 6.89,971.51 ; 6.89,971.51 64.38,971.51 cw(c64.38,897.26) USART5.4@67.46,971.45
  Bottom Layer w6: v1(1051.89,1284.76) v1(1071.89,1284.76)
  Bottom Layer w10: v1(907.76,14.76) v1(930.96,14.76) 931.67,14.05 946.67,14.05 ccw(c1017.39,84.76) 1017.39,-15.24 1091.86,-15.24 1546.18,-15.24 ccw(c1546.18,70.99) 1607.14,10.02 ccw(c1571.54,45.62) 1621.89,45.62 1621.89,98.34 cw(c1721.89,98.34) 1651.18,169.05 1707.6,225.47 ccw(c1636.89,296.19) 1736.89,296.19 1736.89,845.62 ccw(c1717.43,850.76) v3(1731.89,864.76) ; 1091.89,-15.16 v1(1091.89,11.04) v1(1091.89,29.76)
  Bottom Layer w15: v1(-63.16,1624.73) -18.11,1624.73 ; v1(-13.11,1089.76) v1(-38.11,1089.76) -67.53,1119.19 cw(c-5.78,1180.94) -93.11,1180.94 -93.11,1454.76 -18.11,1529.76 -18.11,1624.73 ; v1(1034.49,1540.07) v1@1051.89,1540.07 ; v1(1051.89,1284.76) 1051.89,1453.34 cw(c1151.89,1453.34) 1081.18,1524.05 1102.91,1545.79 ; v1(1051.89,1539.76) v1@1051.89,1540.07 ; v1(1167.83,1685.06) cw(c1167.1,1685.79) 1167.1,1684.76 1132.2,1684.76 ; -18.11,1624.73 50.44,1624.73 ccw(c50.44,1724.73) 121.15,1654.02 123.21,1656.08 cw(c193.92,1585.37) 193.92,1685.37 1131.59,1685.37 1132.2,1684.76 ; v1@1051.89,1540.07 1089.12,1540.07 ccw(c1089.12,1559.58) 1102.91,1545.79 ; 1102.91,1545.79 ccw(c1032.2,1616.5) 1132.2,1616.5 1132.2,1684.76
  other v1: -93.16,1564.73 -63.16,1564.73 -93.16,1594.73 -63.16,1594.73 -93.16,1624.73
DM: R27.2 U1.70 | length 358.6
  Top Layer w6: U1.70@754.09,1092 754.09,1345.88 cw(c854.09,1345.88) 783.38,1416.59 R27.2@801.89,1435.1
DP: R26.2 U1.71 | length 346.4
  Top Layer w6: U1.71@734.41,1092 734.41,1404.97 cw(c777.02,1404.97) R26.2@746.89,1435.1
DRDY: U11.A1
